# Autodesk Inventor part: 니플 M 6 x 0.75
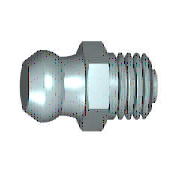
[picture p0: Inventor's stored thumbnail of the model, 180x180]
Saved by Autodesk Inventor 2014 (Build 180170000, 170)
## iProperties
IsCustomPart: 1
Created: 2012-02
Part Number: 니플 M 6 x 0.75
Material: 강철, 연강
Description: 윤활 니플, 원추 유형 A
Document SubType Name: Modeling
Standard: JIS B 1575
Designer: mduedu
Standards Organization: JIS
Language: ko-KR
Size Designation: MT 6 x 0.75
Categories: <MemberInstance><Categories><Category DisplayName="기타 부품" InternalName="5aa15e00-363f-49f2-933f-16f664388e3f" Mnemonic="OTHER"><Category DisplayName="그리스 부속품" I
Density: 7.86 g/cm^3
Mass: 2.07141 g
Surface Area: 3.29319 cm^2
Volume: 0.263539 cm^3
Appearance: 강철
Author: mduedu
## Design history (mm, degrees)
sketch "스케치1"
  geometry: L1 (-8.8, 0)-(-8.8, 2.4); L2 (-8.8, 2.4)-(-7.335, 3.202); L3 (-8.8, 0)-(4.7, 0); L4 (4.7, 0)-(4.7, 1.5); L5 (4.7, 1.5)-(4, 1.5); L6 (4, 1.5)-(4, 3); L7 (4, 3)-(0, 3); L8 (-11.5, 0)-(7.4, 0) reference; L9 (0, -1.733)-(0, 10.398) reference; L10 (-3, 3.5)-(0, 3.5); L11 (0, 3.5)-(0, 3); A1 r 3.3 centre (-6.535, 0) between (-4.789, 2.8) and (-7.335, 3.202); A2 r 6 centre (-6.053, 8.665) between (-4.789, 2.8) and (-3, 3.5)
  constraints: 18 end point, 5 perpendicular, 4 point on circle, 2 centre point, 2 parallel, 2 point on line, 1 collinear, 1 vertical
  dimensions: "d0" = 13.5 distance between parallel lines of L1 L4 (= GL); "d1" = 5.6 diameter of A1.start L3 (= KGB2); "d2" = 0.7 distance between parallel lines of L4 L6 (= PHH); "d3" = 3 diameter of L5 L3 (= 0.5 x NND); "d4" = 6 diameter of L7 L3 (= NND); "d5" = 6.6 dimension on A1 L3 (= KR); "d6" = 4.8 diameter of L1.end L3 (= KGB1); "d7" = 6 radius of A2 (= RBN); "d11" = 7 diameter of L10.start L3 (= SW); "d14" = 3 distance of L10.start L10.end (= KOH); "d15" = 4 distance between parallel lines of L6 L11 (= NLG); "d61" = 7.33505 distance from line of L9 L2.end (computed from KGB1, KR, PHH, GL, NLG, VERS); "d62" = 6.53505 distance from line of L9 A1.centre (computed from NLG, GL, PHH, KR, KGB1)
revolve "본체" sketch "스케치1" stored, may be unused: angle "d25" = 90 deg
sketch "스케치2"
  geometry: L1 (2.021, 3.5)-(4.041, 0); L2 (4.041, 0)-(2.021, -3.5); L3 (2.021, -3.5)-(-2.021, -3.5); L4 (-2.021, -3.5)-(-4.041, 0); L5 (-4.041, 0)-(-2.021, 3.5); L6 (-2.021, 3.5)-(2.021, 3.5); C1 r 3.5 at (0, 0) reference; 1 further point
  constraints: 12 end point, 1 coincident, 1 horizontal, 1 tangent, 11 other
extrude "머리" join sketch "스케치2" distance "d17" = 3 (= KOH); taper "d18" = 0 deg
sketch "스케치3"
  geometry: L1 (2.687, 4.041)-(3, 4.041); L2 (3, 4.041)-(3, 3.5); L3 (3, 3.5)-(2.687, 4.041); L4 (0.313, 4.041)-(0, 4.041); L5 (0, 4.041)-(0, 3.5); L6 (0, 3.5)-(0.313, 4.041); L7 (3.6, 0)-(-0.6, 0) reference; L8 (0, 4.041)-(0, 2.021) reference; L9 (0, 4.041)-(3, 4.041) reference; L10 (3, 3.031)-(3, 4.041) reference
  constraints: 12 end point, 4 collinear, 3 perpendicular, 1 horizontal
  dimensions: "d19" = 3.5 distance from line of L5.end L7 (= 0.5 x SW); "d20" = 3.5 distance from line of L2.end L7 (= 0.5 x SW); "d21" = 30 deg angle of L6 L5; "d22" = 30 deg angle of L2 L3
revolve "모따기1" sketch "스케치3" stored, may be unused: angle "d56" = 90 deg
body "Solid1"
fillet "모깎기1" dims "d8" = 0.2 (= RR)
feature "스레드1" dims "d9" = 3.53991 (= NLG - GAL), "d10" = 0
chamfer "모따기2" distance "d23" = 0.46009 (= -0.5 x GD1 + 0.5 x NND); stored, may be unused: angle "d24" = 45 deg, second distance "d59" = 0.46009 (= -0.5 x GD1 + 0.5 x NND)
other parameters: "NLG" = 4 [user parameter; used in 4 equation terms], "GL" = 13.5 [user parameter; used in 3 equation terms], "NND" = 6 [user parameter; used in 4 equation terms], "KGB1" = 4.8 [user parameter; used in 3 equation terms], "KGB2" = 5.6 [user parameter; used in 1 equation term], "VERS" = 0.8 [user parameter; used in 1 equation term], "KR" = 6.6 [user parameter; used in 3 equation terms], "RBN" = 6 [user parameter; used in 1 equation term], "SW" = 7 [user parameter; used in 3 equation terms], "KOH" = 3 [user parameter; used in 2 equation terms], "GAL" = 0.46009 (= 0.61345 x PTC) [user parameter; used in 1 equation term], "FAWI" = 45 deg [user parameter], "PHH" = 0.7 [user parameter; used in 3 equation terms], "GD1" = 5.07983 (= THREADDIA - 1.2269 x PTC) [user parameter; used in 2 equation terms], "RR" = 0.2 [user parameter; used in 1 equation term], "d12" = 0, "d13" = 0, "GUL" = 0.46009 (= 0.61345 x PTC) [user parameter], "TPU" = 13.33333 (computed from PTC) [user parameter], "DULO" = 1.5 [user parameter], "PTC" = 0.75 [user parameter; used in 4 equation terms], "GEL" = 4 [user parameter], "THREADDIA" = 6 [user parameter; used in 1 equation term], "TOA" = 30 deg [user parameter]
